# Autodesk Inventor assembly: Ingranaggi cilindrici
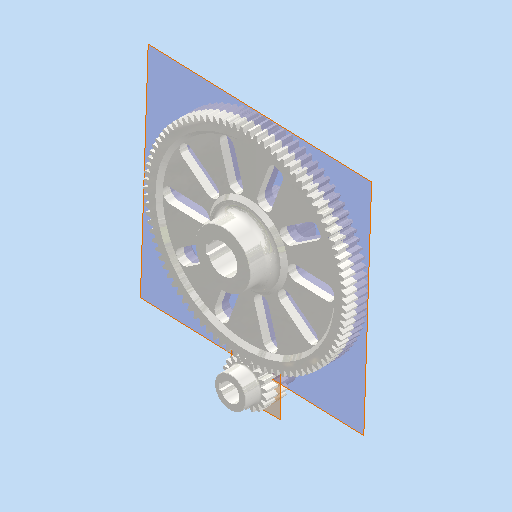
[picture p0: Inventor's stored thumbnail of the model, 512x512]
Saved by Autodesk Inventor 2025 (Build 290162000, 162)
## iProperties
ClientObjectVersion: 1
Created: 2026-05
Part Number: Ingranaggi cilindrici
Document SubType Name: Assembly
Designer: R5800u
Categories: <?xml version="1.0" encoding="UTF-16"?> <MemberInstance><Categories><FamilyTemplate/><ParamToTemplateMap><ParamToTemplate><ParamToTemplate CategoryParameter="//
Author: R5800u
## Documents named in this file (3)
- C:\Users\Ryzen5700u\Desktop\riduttore pompa\Ingranaggi cilindrici1.iam
- C:\Users\Ryzen5700u\Desktop\riduttore pompa\Ingranaggio cilindrico11.ipt
- C:\Users\Ryzen5700u\Desktop\riduttore pompa\Ingranaggio cilindrico21.ipt
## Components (2 placed, 2 different names)
1. Ingranaggio cilindrico1:1 — Rotazione:1
2. Ingranaggio cilindrico2:1 — Rotazione:1
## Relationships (1: RelateRotation 1)
- Rotazione:1 [RelateRotation]: Ingranaggio cilindrico1:1 ↔ Ingranaggio cilindrico2:1
